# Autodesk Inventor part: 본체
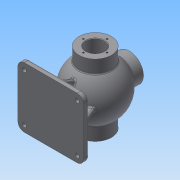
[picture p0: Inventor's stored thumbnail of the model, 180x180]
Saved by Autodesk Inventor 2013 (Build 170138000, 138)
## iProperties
Created: 2018-06
Part Number: 본체
Material: 일반
Document SubType Name: Modeling
Designer: Administrator
Density: 1 g/cm^3
Author: Administrator
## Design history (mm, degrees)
sketch "스케치1"
  geometry: L1 (-68, 0)-(68, 0); A1 r 53 centre (0, 0) between (53, 0) and (-53, 0); A2 r 43 centre (0, 0) between (43, 0) and (-43, 0); 2 further points
  constraints: 4 coincident, 4 point on circle, 4 point on line, 2 centre point, 2 end point, 1 horizontal, 1 midpoint
  dimensions: "d0" = 136 distance of L1.start L1.end; "d1" = 106 diameter of A1; "d2" = 86 diameter of A2
revolve "회전1" sketch "스케치1" stored, may be unused: angle "d3" = 90 deg
node "작업 평면1"
sketch "스케치2"
  geometry: C1 r 31 at (0, 0); 1 further point
  constraints: 1 centre point, 1 coincident
  dimensions: "d5" = 62 diameter of C1
extrude "돌출1" join sketch "스케치2" stored distance "d6" = 10; taper "d7" = 0 deg
hole "구멍1" diameter "d10" = 35; stored, may be unused: countersink angle "d14" = 90 deg, drill point angle "d16" = 118 deg; dims "d8" = 10, "d9" = 10, "d11" = 6, "d12" = 4, "d13" = 2, "d15" = 8
sketch "스케치3"
  geometry: C1 r 17.5 at (0, 0) reference; 1 further point
  constraints: 1 vertical alignment
  dimensions: "d17" = 22.5 distance of C1.centre point (0, 22.5)
hole "구멍2" sketch "스케치3" at (0, 22.5) diameter "d18" = 3.242; stored, may be unused: countersink angle "d22" = 90 deg, drill point angle "d24" = 118 deg; dims "d19" = 12, "d20" = 4, "d21" = 2, "d23" = 15
node "작업 평면2"
sketch "스케치4"
  geometry: C1 r 27 at (0, 0); 1 further point
  constraints: 1 centre point, 1 coincident
  dimensions: "d30" = 54 diameter of C1
extrude "돌출2" join sketch "스케치4" stored distance "d31" = 10; taper "d32" = 0 deg
hole "구멍3" diameter "d35" = 26; stored, may be unused: countersink angle "d39" = 90 deg, drill point angle "d41" = 0 deg; dims "d33" = 10, "d34" = 10, "d36" = 12, "d37" = 4, "d38" = 2, "d40" = 60
sketch "스케치5"
  geometry: C1 r 13 at (0, 0) reference; 1 further point
  constraints: 1 vertical alignment
  dimensions: "d42" = 20 distance of C1.centre point (0, 20)
hole "구멍4" sketch "스케치5" at (0, 20) diameter "d43" = 3.242; stored, may be unused: countersink angle "d47" = 90 deg, drill point angle "d49" = 118 deg; dims "d44" = 9, "d45" = 4, "d46" = 2, "d48" = 11
chamfer "모따기1" distance "d53" = 1; stored, may be unused: second distance "d54" = 2, angle "d55" = 45 deg
node "작업 평면3"
sketch "스케치6"
  geometry: L1 (62.5, 57.5)-(-62.5, 57.5); L2 (-62.5, 57.5)-(-62.5, -57.5); L3 (-62.5, -57.5)-(62.5, -57.5); L4 (62.5, -57.5)-(62.5, 57.5); L5 (62.5, 57.5)-(-62.5, -57.5); L6 (-62.5, 57.5)-(62.5, -57.5); 1 further point
  constraints: 12 end point, 2 midpoint, 2 parallel, 1 horizontal, 1 perpendicular
  dimensions: "d57" = 125 distance of L3.end L2.end; "d58" = 115 distance of L2.end L1.end
extrude "돌출3" join sketch "스케치6" distance "d59" = 10; taper "d60" = 0 deg
sketch "스케치7"
  geometry: L1 (4, -47.5)-(-4, -47.5); L2 (-4, -47.5)-(-4, 47.5); L3 (-4, 47.5)-(4, 47.5); L4 (4, 47.5)-(4, -47.5); L5 (4, -47.5)-(-4, 47.5); L6 (-4, -47.5)-(4, 47.5); L7 (-52.5, -4)-(52.5, -4); L8 (52.5, -4)-(52.5, 4); L9 (52.5, 4)-(-52.5, 4); L10 (-52.5, 4)-(-52.5, -4); L11 (-52.5, -4)-(52.5, 4); L12 (52.5, -4)-(-52.5, 4); 1 further point
  constraints: 24 end point, 4 midpoint, 4 parallel, 2 horizontal, 2 perpendicular
  dimensions: "d61" = 8 distance of L2.end L3.end; "d62" = 95 distance of L1.end L2.end; "d63" = 105 distance of L9.end L8.end; "d64" = 8 distance of L8.end L7.end
extrude "돌출4" join sketch "스케치7" stored distance "d65" = 10; taper "d66" = 0 deg
extrude "돌출5" join sketch "스케치7" stored distance "d67" = 10; taper "d68" = 0 deg
feature "면 기울기1" dims angle "d69" = 22 deg
hole "구멍5" diameter "d72" = 35; stored, may be unused: countersink angle "d76" = 90 deg, drill point angle "d78" = 0 deg; dims "d70" = 10, "d71" = 10, "d73" = 9, "d74" = 4, "d75" = 2, "d77" = 16
hole "구멍6" diameter "d81" = 35; stored, may be unused: countersink angle "d85" = 90 deg, drill point angle "d87" = 0 deg; dims "d79" = 10, "d80" = 10, "d82" = 9, "d83" = 37, "d84" = 1.75, "d86" = 20
fillet "모깎기2" dims "d88" = 12
hole "구멍7" diameter "d91" = 8; stored, may be unused: countersink angle "d95" = 90 deg, drill point angle "d97" = 0 deg; dims "d89" = 10, "d90" = 10, "d92" = 9, "d93" = 12, "d94" = 3, "d96" = 10
fillet "모깎기3" dims "d98" = 3
fillet "모깎기4" dims "d99" = 3
fillet "모깎기5" dims "d100" = 3
node "작업 평면4"
sketch "스케치8"
  geometry: L1 (0, -27)-(17.714, -27) reference; L2 (0, -27)-(0, 27) reference; 2 further points
  constraints: 1 other
  dimensions: "d101" = 27 distance from line of point (10, 0) L1; "d102" = 10 distance from line of point (10, 0) L2
feature "엠보싱1" sketch "스케치8" dims "d0" = 136, "d1" = 106, "d2" = 86, "d103" = 0.5, "d104" = 0
sketch "스케치9"
  geometry: C1 r 17.5 at (0, 0) reference; 1 further point
  constraints: 1 vertical alignment
  dimensions: "d105" = 24 distance of C1.centre point (0, 24)
hole "구멍8" sketch "스케치9" at (0, 24) diameter "d106" = 3.242; stored, may be unused: countersink angle "d110" = 90 deg, drill point angle "d112" = 118 deg; dims "d107" = 16, "d108" = 12, "d109" = 3, "d111" = 19
node "솔리드1"
pattern_circular "원형 패턴1" dims angle "d26" = 360 deg
mirror "대칭1"
pattern_circular "원형 패턴2" dims angle "d51" = 360 deg
mirror "대칭2"
mirror "대칭3"
pattern_circular "원형 패턴3" dims angle "d114" = 360 deg
other parameters: "d4" = 68, "d29" = 65, "d56" = -85
